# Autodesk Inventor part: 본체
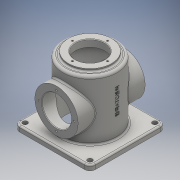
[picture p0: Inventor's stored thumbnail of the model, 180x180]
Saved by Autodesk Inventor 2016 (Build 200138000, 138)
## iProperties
Created: 2019-08
Part Number: 본체
Material: 일반
Document SubType Name: Modeling
Designer: user
Density: 1 g/cm^3
Appearance: 기본값
Author: user
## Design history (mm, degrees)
sketch "스케치1"
  geometry: C1 r 50 at (0, 0); 1 further point
  constraints: 1 centre point, 1 coincident
  dimensions: "d0" = 100 diameter of C1
extrude "돌출1" new body sketch "스케치1" distance "d1" = 120; taper "d2" = 0 deg
sketch "스케치2"
  geometry: C1 r 45 at (0, 0); 1 further point
  constraints: 1 centre point, 1 coincident
  dimensions: "d3" = 90 diameter of C1
extrude "돌출2" cut sketch "스케치2" distance "d4" = 112; taper "d5" = 0 deg
sketch "스케치3"
  geometry: L1 (-60, -70)-(60, -70); L2 (70, -60)-(70, 60); L3 (60, 70)-(-60, 70); L4 (-70, 60)-(-70, -60); L5 (-70, -70)-(70, 70); L6 (70, -70)-(-70, 70); C1 r 50 at (0, 0); A1 r 10 centre (60, 60) between (70, 60) and (60, 70); A2 r 10 centre (-60, 60) between (-60, 70) and (-70, 60); A3 r 10 centre (-60, -60) between (-70, -60) and (-60, -70); A4 r 10 centre (60, -60) between (60, -70) and (70, -60); 1 further point
  constraints: 12 end point, 8 point on circle, 8 point on line, 8 tangent, 5 centre point, 3 equal radius, 2 midpoint, 2 parallel, 2 perpendicular, 1 coincident, 1 horizontal
  dimensions: "d6" = 140 distance of L6.start L5.end; "d7" = 100 diameter of C1; "d10" = 10 radius of A1
extrude "돌출3" join sketch "스케치3" distance "d8" = 10; taper "d9" = 0 deg
sketch "스케치4"
  geometry: C1 r 40 at (0, 0); 1 further point
  constraints: 1 centre point, 1 coincident
  dimensions: "d11" = 80 diameter of C1
extrude "돌출4" join sketch "스케치4" distance "d12" = 5; taper "d13" = 0 deg
hole "구멍1" diameter "d16" = 54; stored, may be unused: countersink angle "d20" = 90 deg, drill point angle "d22" = 118 deg; dims "d14" = 10, "d15" = 10, "d17" = 6, "d18" = 4, "d19" = 2, "d21" = 8
sketch "스케치5"
  geometry: A1 r 32.5 centre (0, 0) between (32.5, 0) and (-32.5, 0); 3 further points
  constraints: 4 point on circle, 1 centre point, 1 coincident
  dimensions: "d23" = 65 diameter of A1
hole "구멍2" sketch "스케치5" at (32.5, 0), (-32.5, 0), (0, 32.5), (0, -32.5) diameter "d24" = 3.242; stored, may be unused: countersink angle "d28" = 90 deg, drill point angle "d30" = 118 deg; dims "d25" = 8, "d26" = 4, "d27" = 2, "d29" = 10
node "작업 평면1"
sketch "스케치6"
  geometry: L1 (60, 0)-(-60, 0) reference; C1 r 40 at (0, 60); 2 further points
  constraints: 1 centre point, 1 midpoint, 1 vertical alignment
  dimensions: "d32" = 80 diameter of C1; "d33" = 60 distance from line of L1 C1.centre
extrude "돌출5" join sketch "스케치6" stored distance "d34" = 10; taper "d35" = 0 deg
sketch "스케치7"
  geometry: 1 further point
hole "구멍3" diameter "d38" = 54; stored, may be unused: countersink angle "d42" = 90 deg, drill point angle "d44" = 118 deg; dims "d36" = 10, "d37" = 10, "d39" = 6, "d40" = 4, "d41" = 2, "d43" = 8
sketch "스케치8"
  geometry: A1 r 32.5 centre (0, 0) between (0, 32.5) and (-32.5, 0); 3 further points
  constraints: 4 point on circle, 1 centre point
  dimensions: "d45" = 65 diameter of A1
hole "구멍4" sketch "스케치8" at (32.5, 0), (0, 32.5), (-32.5, 0), (0, -32.5) diameter "d46" = 3.242; stored, may be unused: countersink angle "d50" = 90 deg, drill point angle "d52" = 118 deg; dims "d47" = 8, "d48" = 4, "d49" = 2, "d51" = 10
sketch "스케치9"
  geometry: A1 r 10 centre (-60, -60) between (-70, -60) and (-60, -70) reference; A2 r 10 centre (60, -60) between (60, -70) and (70, -60) reference; A3 r 10 centre (-60, 60) between (-60, 70) and (-70, 60) reference; A4 r 10 centre (60, 60) between (70, 60) and (60, 70) reference; 5 further points
  constraints: 4 coincident
hole "구멍5" sketch "스케치9" at (60, -60), (60, 60), (-60, -60), (-60, 60) diameter "d53" = 9; stored, may be unused: countersink angle "d57" = 90 deg, drill point angle "d59" = 118 deg; dims "d54" = 8, "d55" = 4, "d56" = 2, "d58" = 10
node "작업 평면2"
sketch "스케치10"
  geometry: L1 (-60, 0)-(60, 0) reference; 4 further points
  constraints: 2 midpoint, 1 vertical alignment, 1 other
  dimensions: "d65" = 70 distance of point (0, 0) point (0, 70)
feature "엠보싱1" sketch "스케치10" dims "d61" = 0.5, "d62" = 0
fillet "모깎기1" dims "d63" = 5, "d64" = 3
chamfer "모따기1" distance "d66" = 1; stored, may be unused: second distance "d67" = 2, angle "d68" = 45 deg
node "솔리드1"
mirror "대칭1"
other parameters: "d31" = -62
